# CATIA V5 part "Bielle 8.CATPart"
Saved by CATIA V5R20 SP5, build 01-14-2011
Part number: Bielle 8
Bounding box of the stored display mesh (mm): x -229.978 to -190.022, y -259.978 to 59.978, z 75 to 85
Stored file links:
  U:\CFAO\Thinkmotion\Bielle 8.CATPart
  U:\CFAO\Thinkmotion\Bras Articule.CATProduct
  U:\CFAO\Thinkmotion\Squelette Bielle 8.CATPart
  J:\Projet Thinkmotion\areckea\Bielle principale.CATPart
  U:\CFAO\Thinkmotion\Squelette Bielle principale.CATPart
  U:\CFAO\Thinkmotion\Squelette Bielle 7.CATPart
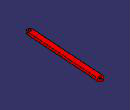
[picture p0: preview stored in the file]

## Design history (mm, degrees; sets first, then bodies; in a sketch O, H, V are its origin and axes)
Set1
  Plane1: linked copy from another document
  Line1: linked copy from another document
  Point1: linked copy from another document
  Point2: linked copy from another document
Body1 (main body)
  Sketch1 on Plane1, origin (0, 0, 80), H (1, 0, 0), V (0, 1, 0)
    line L1 (-210.0221, -250.6652) -> (-190.0221, 49.3348)
    arc A1 centre (-200, 50) radius 10 from (-190.0221, 49.3348) to (-209.9779, 50.6652) ccw
    line L2 (-209.9779, 50.6652) -> (-229.9779, -249.3348)
    arc A2 centre (-220, -250) radius 10 from (-229.9779, -249.3348) to (-210.0221, -250.6652) ccw
    reference projected line E1 (-220, -250) -> (-200, 50) from Line1
    reference projected line E2 (-220, -250) -> (-200, 50) from Line1
    reference projected point E3 (-200, 50) from Point1
    reference projected point E4 (-220, -250) from Point2
    circle A3 centre (-220, -250) radius 5
    circle A4 centre (-200, 50) radius 5
    radius A2 = 10
    radius A3 = 5
    radius A4 = 5
    tangency: A1 L1, L2 A1, A2 L1, A2 L2
    parallelism: L2 L1, L1 E1
    symmetry: L2 L1 E2
    concentricity: E3 A1, E4 A2, A3 A2, A4 A1
  Pad1: profile Sketch1, direction (0, 0, 1), length 5, mirrored extent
